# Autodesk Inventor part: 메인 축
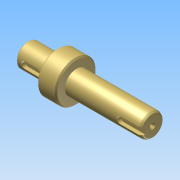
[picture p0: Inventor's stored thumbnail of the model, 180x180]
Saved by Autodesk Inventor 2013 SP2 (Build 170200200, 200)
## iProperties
Created: 2026-07
Part Number: 메인 축
Material: Generic
Document SubType Name: Modeling
Designer: aa
Density: 1 g/cm^3
변환 표준: STEP AP214IS
전처리기: Build: 200, Release: 2013 SP2 Update 6 - Date: Thu 07/17/2014
전송 단위: 밀리미터
불확실성: 0.01
Author: aa
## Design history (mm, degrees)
node "메인 축1"
node "솔리드1"
node "기준1"
